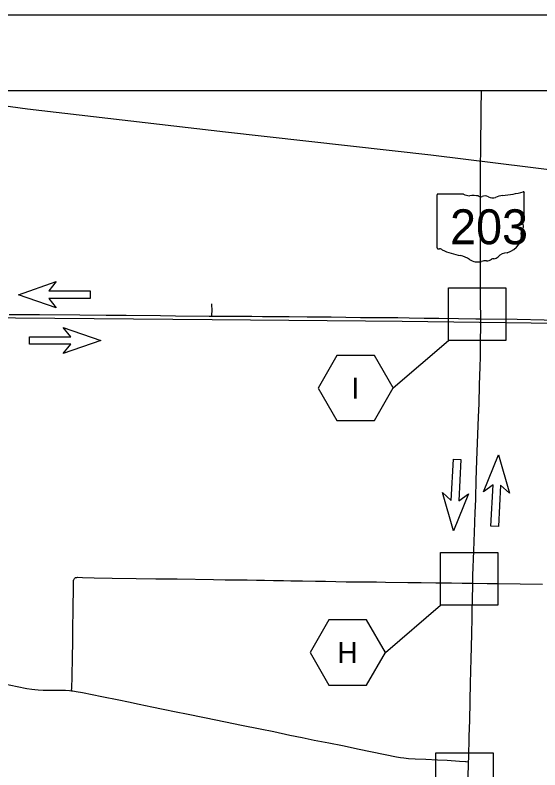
# Model space of a CAD drawing. Extents: x 0 to 680, y 0 to 440.
# Drawn here: x 332.1 to 401.8, y 339.7 to 440 of the extents above; entities that cross this region are included whole.
import ezdxf

# ---------------------------------------------------------------- set-up
doc = ezdxf.new("R2010")
doc.units = 0
for name, color, linetype in [('GM_X_County_Road', 7, 'Continuous'), ('GM_X_State_Location', 7, 'Continuous'), ('GM_X_State_Route', 7, 'Continuous'), ('GM_X_State_Shield', 7, 'Continuous'), ('GM_X_Township_Road', 7, 'Continuous'), ('PM_P_Cells', 7, 'Continuous'), ('RD_X_RR_2', 7, 'Continuous'), ('SH_Border', 7, 'Continuous'), ('SH_Cut_Line', 7, 'Continuous'), ('SH_Text', 7, 'Continuous')]:
    doc.layers.add(name, color=color, linetype=linetype)

msp = doc.modelspace()

# ---------------------------------------------------------------- linework, layer by layer
at = {"layer": 'GM_X_County_Road'}
for points in [[(393.94, 399.66), (393.94, 399.89), (393.92, 401.77), (393.92, 403.96), (393.91, 406.04), (393.92, 407.68), (393.91, 410.41), (393.9, 412.38), (393.9, 415.56), (393.9, 417.74), (393.92, 419.71), (393.89, 419.82), (393.92, 419.93), (393.92, 420.37), (393.94, 421.79), (393.96, 423.98), (393.98, 425.51), (393.99, 427.48), (394.02, 429.89), (394.02, 430)], [(392.88, 364.53), (392.9, 365.55), (393.02, 368.83), (393.14, 372.54), (393.2, 374.07), (393.22, 374.62), (393.26, 375.82), (393.34, 378.22), (393.43, 380.84), (393.64, 386.64), (393.71, 388.38), (393.79, 390.9), (393.87, 393.3), (393.89, 394.61), (393.91, 396.91), (393.93, 398.44), (393.94, 399.21), (393.94, 399.66)], [(339.58, 350.25), (339.59, 350.64), (339.64, 352.06), (339.7, 354.78), (339.73, 356.63), (339.75, 358.81), (339.78, 360.67), (339.8, 361.76), (339.82, 363.39), (339.82, 364.59), (339.84, 364.81), (339.85, 364.91), (339.88, 365.02), (339.9, 365.09), (339.94, 365.17)], [(339.94, 365.17), (340, 365.22), (340.05, 365.26), (340.1, 365.28), (340.16, 365.3), (340.25, 365.31), (340.37, 365.32), (341.02, 365.31), (342.56, 365.27), (344.96, 365.22), (348.14, 365.17), (350.77, 365.13), (353.61, 365.1), (358.43, 365.03), (359.96, 365), (360.95, 364.99), (361.82, 364.99), (362.92, 364.97), (364.12, 364.95), (365.21, 364.93), (366.42, 364.9), (367.73, 364.88), (368.71, 364.86), (370.25, 364.84), (372, 364.81), (373.31, 364.79), (376.05, 364.73), (377.47, 364.73), (378.35, 364.72), (380.1, 364.7), (381.3, 364.69), (384.26, 364.65), (386.01, 364.63), (387.98, 364.6), (390.06, 364.57), (391.48, 364.55), (392.26, 364.54), (392.88, 364.53)], [(392.32, 340.82), (392.34, 341.29), (392.41, 344.24), (392.47, 346.32), (392.59, 351.34), (392.62, 352.76), (392.66, 354.62), (392.69, 355.93), (392.73, 358.01), (392.78, 359.76), (392.8, 360.96), (392.83, 362.49), (392.87, 364.13), (392.88, 364.53)], [(392.88, 364.53), (394.79, 364.51), (396.22, 364.49), (402.12, 364.41)], [(322.27, 352.88), (323.55, 352.58), (325.26, 352.22), (326.44, 351.99), (328.37, 351.6), (329.77, 351.34), (332.35, 350.83), (333.63, 350.57), (334.28, 350.46), (334.71, 350.41), (335.14, 350.37), (335.8, 350.35), (337.66, 350.33), (338.75, 350.31), (339.3, 350.28), (339.58, 350.25)], [(339.58, 350.25), (339.74, 350.24), (340.17, 350.17), (341.03, 350.01), (343.61, 349.49), (345.86, 349.03), (347.14, 348.76), (348.54, 348.48), (350.25, 348.12), (351.75, 347.82), (353.47, 347.46), (354.86, 347.18), (357.22, 346.7), (360.01, 346.14), (362.15, 345.7), (364.62, 345.19), (366.44, 344.82), (368.58, 344.37), (370.19, 344.04), (371.79, 343.71), (373.73, 343.33), (375.55, 342.96), (377.8, 342.49), (382.73, 341.48), (383.27, 341.39), (383.7, 341.33), (384.35, 341.27), (385.22, 341.22), (386.65, 341.16), (388.18, 341.08), (389.49, 341.01), (391.13, 340.92), (391.89, 340.86), (392, 340.85), (392.32, 340.82)], [(392.24, 337.91), (392.25, 338.56), (392.32, 340.82)]]:
    msp.add_lwpolyline(points, dxfattribs=at)
at = {"layer": 'GM_X_State_Route'}
for p, q in [((382.32, 390.48), (389.66, 396.77)), ((381.26, 355.35), (388.59, 361.63))]:
    msp.add_line(p, q, dxfattribs=at)
for points in [[(393.94, 399.66), (393.94, 399.89), (393.92, 401.77), (393.92, 403.96), (393.91, 406.04), (393.92, 407.68), (393.91, 410.41), (393.9, 412.38), (393.9, 415.56), (393.9, 417.74), (393.92, 419.71), (393.89, 419.82), (393.92, 419.93), (393.92, 420.37), (393.94, 421.79), (393.96, 423.98), (393.98, 425.51), (393.99, 427.48), (394.02, 429.89), (394.02, 430)], [(331.27, 400.25), (335.32, 400.21), (340.68, 400.18), (344.18, 400.14), (346.81, 400.12), (351.4, 400.08), (353.37, 400.07), (357.85, 400.03), (358.22, 400.03), (359.93, 400.02), (361.57, 400), (363.54, 399.99), (364.96, 399.97), (366.6, 399.95), (368.46, 399.95), (370.87, 399.93), (374.04, 399.9), (377.98, 399.85), (380.71, 399.82), (382.9, 399.81), (384.43, 399.78), (386.4, 399.75), (388.37, 399.73), (390.99, 399.69), (393.29, 399.67), (393.94, 399.66)], [(392.88, 364.53), (392.9, 365.55), (393.02, 368.83), (393.14, 372.54), (393.2, 374.07), (393.22, 374.62), (393.26, 375.82), (393.34, 378.22), (393.43, 380.84), (393.64, 386.64), (393.71, 388.38), (393.79, 390.9), (393.87, 393.3), (393.89, 394.61), (393.91, 396.91), (393.93, 398.44), (393.94, 399.21), (393.94, 399.66)], [(393.94, 399.66), (398.76, 399.59), (402.37, 399.53), (405.32, 399.49), (406.74, 399.47), (409.48, 399.43), (413.52, 399.39), (416.58, 399.34), (418.88, 399.31), (419.92, 399.3), (423.04, 399.27), (425.44, 399.23), (427.19, 399.2), (429.93, 399.16), (432.66, 399.13), (434.96, 399.11), (437.04, 399.07), (438.79, 399.05), (441.41, 399.02), (443.49, 398.99), (446.39, 398.94)], [(392.32, 340.82), (392.34, 341.29), (392.41, 344.24), (392.47, 346.32), (392.59, 351.34), (392.62, 352.76), (392.66, 354.62), (392.69, 355.93), (392.73, 358.01), (392.78, 359.76), (392.8, 360.96), (392.83, 362.49), (392.87, 364.13), (392.88, 364.53)], [(392.24, 337.91), (392.25, 338.56), (392.32, 340.82)]]:
    msp.add_lwpolyline(points, dxfattribs=at)
for points in [[(379.81, 394.8), (374.81, 394.79), (372.32, 390.45), (374.83, 386.13), (379.83, 386.14), (382.32, 390.48)], [(378.74, 359.67), (373.74, 359.66), (371.26, 355.32), (373.77, 351), (378.77, 351.01), (381.26, 355.35)]]:
    msp.add_lwpolyline(points, close=True, dxfattribs=at)
at = {"layer": 'GM_X_State_Shield'}
for p, q in [((388.12, 416.11), (388.12, 409.07)), ((391.63, 416.23), (388.24, 416.23)), ((399.72, 412.72), (399.72, 416.41)), ((399.72, 412.72), (399.72, 412.72))]:
    msp.add_line(p, q, dxfattribs=at)
for centre, major_axis, start_param, end_param in [((388.26, 416.13), (0.134, 0), 1.712693, 3.28349), ((392.44, 417.05), (1.3, 0), 4.042523, 4.731795), ((395.59, 425.84), (12.3, 0), 4.814394, 5.042369), ((399.6, 416.42), (0.129, 0), 6.141152, 7.989035), ((392.88, 412.28), (4.68, 0), 1.404758, 1.657858), ((393.94, 416.16), (0.376, 0), 3.836095, 5.185415), ((394.49, 415.35), (0.782, 0), 0.950623, 2.079405), ((395.5, 416.46), (0.941, 0), 4.081561, 5.145723), ((397.16, 414.08), (2.48, 0), 1.699011, 2.107814), ((399.69, 412.45), (0.2, 0), 1.883978, 3.671073), ((398.42, 411.98), (1.2, 0), 5.934695, 6.695948), ((399.59, 412.71), (0.138, 0), 5.05454, 6.418171), ((396.28, 410.71), (3.08, 0), 5.101752, 6.440018), ((400.19, 411.18), (0.873, 0), 2.387724, 3.262537), ((388.26, 409.05), (0.136, 0), 3.00124, 4.508301), ((388.28, 409.77), (1.03, 0), 4.665946, 4.897461), ((388.49, 408.66), (0.373, 0), 0.519207, 1.627899), ((393.2, 414.99), (8.88, 0), 4.195997, 4.488961), ((397.58, 407.09), (1.69, 0), 1.647645, 2.488434), ((390.55, 405.9), (2.78, 0), 0.823519, 1.323587), ((393.56, 408.62), (1.76, 0), 4.026481, 4.996735), ((394.58, 406.19), (1.45, 0), 1.495662, 1.94098), ((394.71, 408.1), (0.94, 0), 4.691044, 5.507374), ((395.56, 407.41), (0.265, 0), 1.147584, 2.315152), ((395.44, 408.38), (0.994, 0), 4.937069, 5.64225)]:
    msp.add_ellipse(centre, major_axis=major_axis, ratio=0.8, start_param=start_param, end_param=end_param, dxfattribs=at)
at = {"layer": 'GM_X_Township_Road'}
msp.add_line((358.22, 401.25), (358.19, 401.64), dxfattribs=at)
msp.add_lwpolyline([(358.22, 400.03), (358.22, 400.17), (358.23, 400.74), (358.23, 401.08), (358.22, 401.25)], dxfattribs=at)
at = {"layer": 'PM_P_Cells'}
for p, q in [((332.54, 402.86), (337.54, 404.6)), ((337.54, 404.6), (336.54, 403.36)), ((336.54, 403.36), (342.04, 403.36)), ((342.04, 403.36), (342.04, 402.36)), ((332.54, 402.86), (332.54, 402.86)), ((337.54, 401.13), (332.54, 402.86)), ((342.04, 402.36), (336.54, 402.36)), ((336.54, 402.36), (337.54, 401.13)), ((342.04, 402.86), (342.04, 402.86)), ((339.47, 397.28), (338.47, 398.52)), ((338.47, 398.52), (343.47, 396.78)), ((333.97, 396.28), (333.97, 397.28)), ((333.97, 397.28), (339.47, 397.28)), ((333.97, 396.78), (333.97, 396.78)), ((339.47, 396.28), (333.97, 396.28)), ((343.47, 396.78), (338.47, 395.05)), ((338.47, 395.05), (339.47, 396.28)), ((343.47, 396.78), (343.47, 396.78)), ((390.02, 375.51), (390.31, 381)), ((390.31, 381), (391.31, 380.95)), ((394.29, 376.67), (396.28, 381.58)), ((396.28, 381.58), (396.28, 381.58)), ((396.28, 381.58), (397.76, 376.49)), ((390.81, 380.97), (390.81, 380.97)), ((391.31, 380.95), (391.02, 375.46)), ((395.58, 377.61), (394.29, 376.67)), ((395.29, 372.12), (395.58, 377.61)), ((396.57, 377.56), (396.29, 372.06)), ((397.76, 376.49), (396.57, 377.56)), ((390.32, 371.49), (388.84, 376.57)), ((388.84, 376.57), (390.02, 375.51)), ((392.31, 376.39), (390.32, 371.49)), ((391.02, 375.46), (392.31, 376.39)), ((396.29, 372.06), (395.29, 372.12)), ((395.79, 372.09), (395.79, 372.09)), ((390.32, 371.49), (390.32, 371.49))]:
    msp.add_line(p, q, dxfattribs=at)
at = {"layer": 'RD_X_RR_2'}
for points in [[(313.66, 430), (323.68, 428.91), (333.73, 427.55), (360.02, 424.5), (387.32, 421.44), (413.77, 418.16), (438.79, 415.43), (466.92, 412.47)], [(466.92, 398.36), (463.84, 398.36), (452.25, 398.42), (444.84, 398.49), (436.74, 398.59), (431.01, 398.67), (423, 398.78), (410.9, 398.93), (383.5, 399.29), (378.63, 399.34), (358.23, 399.54), (332.13, 399.75), (318.98, 399.86)]]:
    msp.add_lwpolyline(points, dxfattribs=at)
at = {"layer": 'SH_Border'}
for points in [[(30, 430), (670, 430), (670, 10), (30, 10)], [(389.66, 403.77), (397.28, 403.77), (397.28, 396.77), (389.66, 396.77)], [(388.59, 368.63), (396.22, 368.63), (396.22, 361.63), (388.59, 361.63)], [(387.96, 342.01), (395.58, 342.01), (395.58, 335.01), (387.96, 335.01)]]:
    msp.add_lwpolyline(points, close=True, dxfattribs=at)
at = {"layer": 'SH_Cut_Line'}
msp.add_lwpolyline([(0, 0), (680, 0), (680, 440), (0, 440)], close=True, dxfattribs=at)
at = {"layer": 'SH_Text'}
msp.add_lwpolyline([(30, 430), (466.92, 430), (466.92, 291.27), (342.9, 138.72), (30, 138.72)], close=True, dxfattribs=at)

# ---------------------------------------------------------------- texts
at = {"layer": 'GM_X_State_Location'}
msp.add_text('203', height=0.00667, rotation=0, dxfattribs=at).set_placement((391.66, 428.34))
for s in ['s', 'r']:
    msp.add_text(s, height=0.00667, dxfattribs=at).set_placement((394.02, 428.83))
at = {"layer": 'GM_X_State_Route'}
for s, p in [('I', (376.77, 389.06)), ('H', (374.89, 353.93))]:
    msp.add_text(s, height=2.8, dxfattribs=at).set_placement(p)
at = {"layer": 'GM_X_State_Shield'}
msp.add_text('203', height=4.641, dxfattribs=at).set_placement((389.86, 409.56))

doc.saveas('drawing.dxf')
